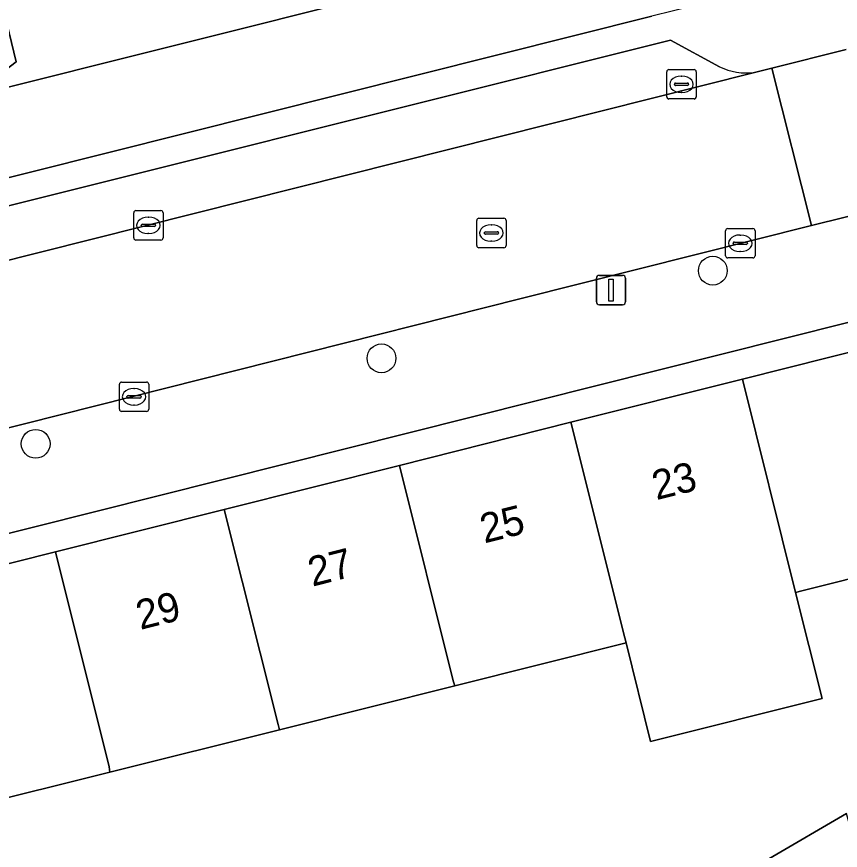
# Model space of a CAD drawing. Extents: x 162523 to 163266, y 381230 to 382050.
# Drawn here: x 162886.68 to 162914.69, y 381712.19 to 381740.55 of the extents above; entities that cross this region are included whole.
import ezdxf

# ---------------------------------------------------------------- set-up
doc = ezdxf.new("R2010")
doc.units = 0
for name, color, linetype in [('IMGEO_Boom', 7, 'Continuous'), ('IMGEO_Erf', 7, 'Continuous'), ('IMGEO_Groenvoorziening', 7, 'Continuous'), ('IMGEO_Kolk', 7, 'Continuous'), ('IMGEO_Lichtmast', 7, 'Continuous'), ('IMGEO_Pand', 7, 'Continuous'), ('IMGEO_Pand_nummerreeks', 7, 'Continuous'), ('IMGEO_Parkeervlak_open', 7, 'Continuous'), ('IMGEO_Rijbaan_lokaal_open', 7, 'Continuous'), ('IMGEO_Rioolput', 7, 'Continuous'), ('IMGEO_Voetpad_open', 7, 'Continuous')]:
    doc.layers.add(name, color=color, linetype=linetype)

msp = doc.modelspace()

# ---------------------------------------------------------------- linework, layer by layer
at = {"layer": 'IMGEO_Boom'}
for centre in [(162910.348, 381731.905), (162899.082, 381728.924), (162887.322, 381726.017)]:
    msp.add_circle(centre, 0.489, dxfattribs=at)
at = {"layer": 'IMGEO_Erf'}
for points in [[(162917.061, 381730.678), (162870.187, 381718.896), (162870.429, 381717.925), (162876.255, 381719.389), (162882.273, 381720.902), (162887.992, 381722.34), (162893.737, 381723.784), (162899.698, 381725.282), (162905.526, 381726.747), (162911.356, 381728.212), (162917.303, 381729.707)], [(162916.309, 381721.748), (162913.374, 381721.014), (162913.166, 381720.962), (162914.067, 381717.352), (162908.235, 381715.887), (162907.404, 381719.242), (162901.574, 381717.783), (162895.614, 381716.291), (162889.848, 381714.848), (162885.065, 381713.651), (162884.162, 381713.425), (162885.438, 381710.232)], [(162909.615, 381710.354), (162914.896, 381713.442)]]:
    msp.add_lwpolyline(points, dxfattribs=at)
at = {"layer": 'IMGEO_Groenvoorziening'}
msp.add_lwpolyline([(162896.202, 381755.567), (162880.2, 381750.72), (162883.952, 381750.168), (162886.105, 381741.272), (162886.654, 381739.004), (162885.1, 381737.835), (162899.104, 381741.349)], close=True, dxfattribs=at)
for points in [[(162899.104, 381741.349), (162885.1, 381737.835), (162886.654, 381739.004), (162886.105, 381741.272)], [(162884.187, 381740.697), (162884.401, 381739.811), (162879.251, 381735.937), (162879.866, 381733.428), (162881.805, 381733.915), (162908.281, 381740.559)]]:
    msp.add_lwpolyline(points, dxfattribs=at)
at = {"layer": 'IMGEO_Kolk'}
for p, q in [((162908.783, 381737.819), (162908.783, 381738.671)), ((162908.858, 381738.745), (162909.71, 381738.745)), ((162909.784, 381738.671), (162909.784, 381737.819)), ((162909.271, 381738.525), (162909.296, 381738.525)), ((162909.042, 381738.239), (162909.042, 381738.251)), ((162909.48, 381738.202), (162909.082, 381738.202)), ((162909.085, 381738.288), (162909.483, 381738.288)), ((162909.526, 381738.251), (162909.526, 381738.239)), ((162909.294, 381737.965), (162909.269, 381737.965)), ((162909.71, 381737.745), (162908.858, 381737.745)), ((162890.655, 381733.021), (162890.655, 381733.873)), ((162890.73, 381733.947), (162891.582, 381733.947)), ((162891.656, 381733.873), (162891.656, 381733.021)), ((162891.143, 381733.727), (162891.168, 381733.727)), ((162890.914, 381733.441), (162890.914, 381733.453)), ((162891.352, 381733.404), (162890.954, 381733.404)), ((162890.957, 381733.49), (162891.355, 381733.49)), ((162891.398, 381733.453), (162891.398, 381733.441)), ((162910.859, 381733.337), (162911.711, 381733.337)), ((162891.166, 381733.167), (162891.141, 381733.167)), ((162910.784, 381732.411), (162910.784, 381733.263)), ((162911.272, 381733.117), (162911.297, 381733.117)), ((162911.785, 381733.263), (162911.785, 381732.411)), ((162891.582, 381732.947), (162890.73, 381732.947)), ((162911.043, 381732.831), (162911.043, 381732.843)), ((162911.481, 381732.794), (162911.083, 381732.794)), ((162911.086, 381732.88), (162911.484, 381732.88)), ((162911.527, 381732.843), (162911.527, 381732.831)), ((162911.295, 381732.557), (162911.27, 381732.557)), ((162911.711, 381732.337), (162910.859, 381732.337)), ((162890.168, 381727.189), (162890.168, 381728.041)), ((162890.243, 381728.115), (162891.095, 381728.115)), ((162890.656, 381727.895), (162890.681, 381727.895)), ((162891.169, 381728.041), (162891.169, 381727.189)), ((162890.427, 381727.609), (162890.427, 381727.621)), ((162890.47, 381727.658), (162890.868, 381727.658)), ((162890.911, 381727.621), (162890.911, 381727.609)), ((162890.865, 381727.572), (162890.467, 381727.572)), ((162890.679, 381727.335), (162890.654, 381727.335)), ((162891.095, 381727.115), (162890.243, 381727.115))]:
    msp.add_line(p, q, dxfattribs=at)
for points in [[(162908.783, 381737.819), (162908.783, 381738.671)], [(162908.858, 381738.745), (162909.71, 381738.745)], [(162909.784, 381738.671), (162909.784, 381737.819)], [(162909.71, 381737.745), (162908.858, 381737.745)], [(162890.655, 381733.021), (162890.655, 381733.873)], [(162890.73, 381733.947), (162891.582, 381733.947)], [(162891.656, 381733.873), (162891.656, 381733.021)], [(162910.859, 381733.337), (162911.711, 381733.337)], [(162910.784, 381732.411), (162910.784, 381733.263)], [(162911.785, 381733.263), (162911.785, 381732.411)], [(162891.582, 381732.947), (162890.73, 381732.947)], [(162911.711, 381732.337), (162910.859, 381732.337)], [(162890.168, 381727.189), (162890.168, 381728.041)], [(162890.243, 381728.115), (162891.095, 381728.115)], [(162891.169, 381728.041), (162891.169, 381727.189)], [(162891.095, 381727.115), (162890.243, 381727.115)]]:
    msp.add_lwpolyline(points, dxfattribs=at)
for centre, radius, start, end in [((162908.86, 381738.669), 0.0765, 91.552, 178.448), ((162908.86, 381738.669), 0.0765, 91.552, 178.448), ((162909.708, 381738.669), 0.0765, 1.552, 88.448), ((162909.708, 381738.669), 0.0765, 1.552, 88.448), ((162909.082, 381738.248), 0.0403, 85.8775, 175.7526), ((162909.079, 381738.238), 0.0366, 178.938, 274.7102), ((162909.483, 381738.245), 0.043, 264.8664, 352.4533), ((162909.487, 381738.25), 0.0386, 1.7309, 96.639), ((162908.86, 381737.821), 0.0765, 181.552, 268.448), ((162908.86, 381737.821), 0.0765, 181.552, 268.448), ((162909.708, 381737.821), 0.0765, 271.552, 358.448), ((162909.708, 381737.821), 0.0765, 271.552, 358.448), ((162890.732, 381733.871), 0.0765, 91.552, 178.448), ((162890.732, 381733.871), 0.0765, 91.552, 178.448), ((162891.58, 381733.871), 0.0765, 1.552, 88.448), ((162891.58, 381733.871), 0.0765, 1.552, 88.448), ((162890.954, 381733.45), 0.0403, 85.8775, 175.7526), ((162890.951, 381733.44), 0.0366, 178.938, 274.7102), ((162891.355, 381733.447), 0.043, 264.8664, 352.4533), ((162891.359, 381733.452), 0.0386, 1.7309, 96.639), ((162910.861, 381733.261), 0.0765, 91.552, 178.448), ((162910.861, 381733.261), 0.0765, 91.552, 178.448), ((162911.709, 381733.261), 0.0765, 1.552, 88.448), ((162911.709, 381733.261), 0.0765, 1.552, 88.448), ((162890.732, 381733.023), 0.0765, 181.552, 268.448), ((162890.732, 381733.023), 0.0765, 181.552, 268.448), ((162891.58, 381733.023), 0.0765, 271.552, 358.448), ((162891.58, 381733.023), 0.0765, 271.552, 358.448), ((162911.083, 381732.84), 0.0403, 85.8775, 175.7526), ((162911.08, 381732.83), 0.0366, 178.938, 274.7102), ((162911.484, 381732.837), 0.043, 264.8664, 352.4533), ((162911.488, 381732.842), 0.0386, 1.7309, 96.639), ((162910.861, 381732.413), 0.0765, 181.552, 268.448), ((162910.861, 381732.413), 0.0765, 181.552, 268.448), ((162911.709, 381732.413), 0.0765, 271.552, 358.448), ((162911.709, 381732.413), 0.0765, 271.552, 358.448), ((162890.245, 381728.039), 0.0765, 91.552, 178.448), ((162890.245, 381728.039), 0.0765, 91.552, 178.448), ((162891.093, 381728.039), 0.0765, 1.552, 88.448), ((162891.093, 381728.039), 0.0765, 1.552, 88.448), ((162890.467, 381727.618), 0.0403, 85.8775, 175.7526), ((162890.464, 381727.608), 0.0366, 178.938, 274.7102), ((162890.868, 381727.615), 0.043, 264.8664, 352.4533), ((162890.872, 381727.62), 0.0386, 1.7309, 96.639), ((162890.245, 381727.191), 0.0765, 181.552, 268.448), ((162890.245, 381727.191), 0.0765, 181.552, 268.448), ((162891.093, 381727.191), 0.0765, 271.552, 358.448), ((162891.093, 381727.191), 0.0765, 271.552, 358.448)]:
    msp.add_arc(centre, radius, start, end, dxfattribs=at)
for centre, major_axis, ratio, start_param, end_param in [((162909.27, 381738.245), (-0.387, 0.002), 0.722429, 4.712389, 7.853982), ((162909.295, 381738.245), (-0.39, 0.002), 0.717154, 1.570796, 4.712389), ((162891.142, 381733.447), (-0.387, 0.002), 0.722429, 4.712389, 7.853982), ((162891.167, 381733.447), (-0.39, 0.002), 0.717154, 1.570796, 4.712389), ((162911.271, 381732.837), (-0.387, 0.002), 0.722429, 4.712389, 7.853982), ((162911.296, 381732.837), (-0.39, 0.002), 0.717154, 1.570796, 4.712389), ((162890.655, 381727.615), (-0.387, 0.002), 0.722429, 4.712389, 7.853982), ((162890.68, 381727.615), (-0.39, 0.002), 0.717154, 1.570796, 4.712389)]:
    msp.add_ellipse(centre, major_axis=major_axis, ratio=ratio, start_param=start_param, end_param=end_param, dxfattribs=at)
at = {"layer": 'IMGEO_Lichtmast'}
for p, q in [((162906.391, 381730.846), (162906.391, 381731.646)), ((162906.391, 381731.646), (162906.391, 381730.846)), ((162906.491, 381731.746), (162907.281, 381731.746)), ((162907.281, 381731.746), (162906.491, 381731.746)), ((162907.381, 381731.646), (162907.381, 381730.846)), ((162907.381, 381730.846), (162907.381, 381731.646)), ((162907.281, 381730.746), (162906.491, 381730.746)), ((162906.491, 381730.746), (162907.281, 381730.746))]:
    msp.add_line(p, q, dxfattribs=at)
msp.add_lwpolyline([(162906.811, 381731.621), (162906.961, 381731.621), (162906.961, 381730.871), (162906.811, 381730.871), (162906.811, 381731.621)], dxfattribs=at)
for centre, start, end in [((162906.491, 381731.646), 90, 180), ((162906.491, 381731.646), 90, 180), ((162907.281, 381731.646), 0, 90), ((162907.281, 381731.646), 360, 90), ((162906.491, 381730.846), 180, 270), ((162906.491, 381730.846), 180, 270), ((162907.281, 381730.846), 270, 0), ((162907.281, 381730.846), 270, 0)]:
    msp.add_arc(centre, 0.1, start, end, dxfattribs=at)
at = {"layer": 'IMGEO_Pand'}
for points in [[(162917.303, 381729.707), (162911.356, 381728.212), (162913.166, 381720.962), (162913.374, 381721.014), (162916.309, 381721.748), (162917.456, 381717.169), (162919.351, 381717.651), (162920.254, 381717.88)], [(162911.356, 381728.212), (162905.526, 381726.747), (162907.354, 381719.418), (162907.404, 381719.242), (162908.235, 381715.887), (162914.067, 381717.352), (162913.166, 381720.962)], [(162905.526, 381726.747), (162899.698, 381725.282), (162901.525, 381717.957), (162901.574, 381717.783), (162907.404, 381719.242), (162907.354, 381719.418)], [(162901.574, 381717.783), (162901.525, 381717.957), (162899.698, 381725.282), (162893.737, 381723.784), (162895.564, 381716.463), (162895.614, 381716.291)], [(162887.992, 381722.34), (162889.817, 381715.023), (162889.848, 381714.848), (162895.614, 381716.291), (162895.564, 381716.463), (162893.737, 381723.784)], [(162887.992, 381722.34), (162882.273, 381720.902), (162884.096, 381713.589), (162884.162, 381713.425), (162885.065, 381713.651), (162889.848, 381714.848), (162889.817, 381715.023)], [(162915.618, 381710.782), (162914.896, 381713.442), (162909.615, 381710.354), (162909.96, 381708.916), (162911.914, 381707.002)]]:
    msp.add_lwpolyline(points, close=True, dxfattribs=at)
at = {"layer": 'IMGEO_Parkeervlak_open'}
for points in [[(162910.582, 381738.844), (162908.913, 381739.751), (162872.672, 381730.67)], [(162870.178, 381728.18), (162911.765, 381738.648)]]:
    msp.add_lwpolyline(points, dxfattribs=at)
msp.add_arc((162911.488, 381740.646), 2.017, 243.3022, 277.8831, dxfattribs=at)
at = {"layer": 'IMGEO_Rijbaan_lokaal_open'}
msp.add_lwpolyline([(162914.881, 381739.432), (162912.355, 381738.788), (162913.701, 381733.445), (162915.948, 381734)], dxfattribs=at)
msp.add_lwpolyline([(162869.37, 381725.142), (162870.042, 381722.432), (162903.836, 381730.962), (162913.701, 381733.445), (162912.355, 381738.788), (162911.765, 381738.648), (162870.178, 381728.18), (162868.698, 381727.851)], close=True, dxfattribs=at)
at = {"layer": 'IMGEO_Rioolput'}
for p, q in [((162902.319, 381732.761), (162902.319, 381733.613)), ((162902.394, 381733.687), (162903.246, 381733.687)), ((162903.32, 381733.613), (162903.32, 381732.761)), ((162902.807, 381733.467), (162902.832, 381733.467)), ((162902.578, 381733.181), (162902.578, 381733.193)), ((162903.016, 381733.144), (162902.618, 381733.144)), ((162902.621, 381733.23), (162903.019, 381733.23)), ((162903.062, 381733.193), (162903.062, 381733.181)), ((162902.83, 381732.907), (162902.805, 381732.907)), ((162903.246, 381732.687), (162902.394, 381732.687))]:
    msp.add_line(p, q, dxfattribs=at)
for points in [[(162902.319, 381732.761), (162902.319, 381733.613)], [(162902.394, 381733.687), (162903.246, 381733.687)], [(162903.32, 381733.613), (162903.32, 381732.761)], [(162903.246, 381732.687), (162902.394, 381732.687)]]:
    msp.add_lwpolyline(points, dxfattribs=at)
for centre, radius, start, end in [((162902.396, 381733.611), 0.0765, 91.552, 178.448), ((162902.396, 381733.611), 0.0765, 91.552, 178.448), ((162903.244, 381733.611), 0.0765, 1.552, 88.448), ((162903.244, 381733.611), 0.0765, 1.552, 88.448), ((162902.618, 381733.19), 0.0403, 85.8775, 175.7526), ((162902.615, 381733.18), 0.0366, 178.938, 274.7102), ((162903.019, 381733.187), 0.043, 264.8664, 352.4533), ((162903.023, 381733.192), 0.0386, 1.7309, 96.639), ((162902.396, 381732.763), 0.0765, 181.552, 268.448), ((162902.396, 381732.763), 0.0765, 181.552, 268.448), ((162903.244, 381732.763), 0.0765, 271.552, 358.448), ((162903.244, 381732.763), 0.0765, 271.552, 358.448)]:
    msp.add_arc(centre, radius, start, end, dxfattribs=at)
for centre, major_axis, ratio, start_param, end_param in [((162902.806, 381733.187), (-0.387, 0.002), 0.722429, 4.712389, 7.853982), ((162902.831, 381733.187), (-0.39, 0.002), 0.717154, 1.570796, 4.712389)]:
    msp.add_ellipse(centre, major_axis=major_axis, ratio=ratio, start_param=start_param, end_param=end_param, dxfattribs=at)
at = {"layer": 'IMGEO_Voetpad_open'}
for points in [[(162914.172, 381742.02), (162908.281, 381740.559), (162881.805, 381733.915), (162879.866, 381733.428), (162879.024, 381733.217), (162876.48, 381732.579), (162874.384, 381732.053), (162869.74, 381730.888), (162864.696, 381729.623), (162862.665, 381729.114), (162861.746, 381728.912), (162814.181, 381717.01), (162811.797, 381716.414), (162810.922, 381716.2), (162800.262, 381713.533)], [(162872.672, 381730.67), (162908.913, 381739.751), (162910.582, 381738.844)], [(162911.765, 381738.648), (162912.355, 381738.788), (162914.881, 381739.432)], [(162915.948, 381734), (162913.701, 381733.445), (162903.836, 381730.962), (162870.042, 381722.432), (162869.37, 381725.142), (162866.441, 381724.384), (162867.118, 381721.675), (162860.243, 381719.934), (162859.564, 381722.636), (162856.627, 381721.906), (162857.3, 381719.211), (162850.143, 381717.392), (162834.93, 381713.565), (162820.665, 381709.939), (162809.05, 381707.004), (162801.406, 381705.07), (162800.493, 381701.494), (162859.084, 381716.26)], [(162859.084, 381716.26), (162862.821, 381717.136), (162866.25, 381718.01), (162870.187, 381718.896), (162917.061, 381730.678), (162921.776, 381731.877)]]:
    msp.add_lwpolyline(points, dxfattribs=at)
msp.add_arc((162911.488, 381740.646), 2.017, 243.3022, 277.8831, dxfattribs=at)

# ---------------------------------------------------------------- texts
at = {"layer": 'IMGEO_Pand_nummerreeks'}
for s, rotation, p in [('23', 14.112, (162908.43, 381724.095)), ('25', 14.1093, (162902.579, 381722.624)), ('27', 14.1093, (162896.729, 381721.154)), ('29', 14.1093, (162890.879, 381719.683))]:
    msp.add_text(s, height=1, rotation=rotation, dxfattribs=at).set_placement(p)

doc.saveas('drawing.dxf')
